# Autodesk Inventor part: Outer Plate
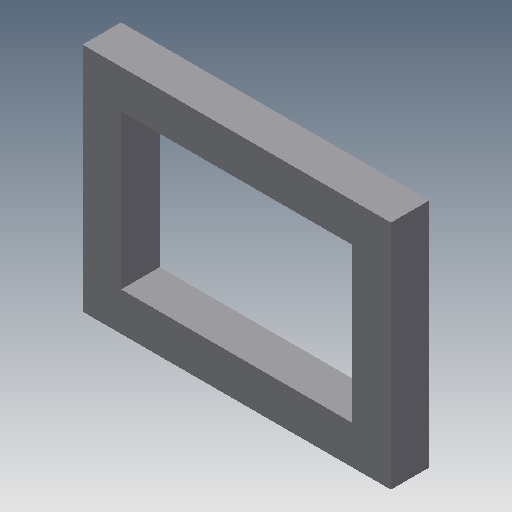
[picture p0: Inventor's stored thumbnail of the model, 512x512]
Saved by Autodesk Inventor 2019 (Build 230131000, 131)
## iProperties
Created: 2010-04
Part Number: Outer Plate
Document SubType Name: Modeling
Designer: CADSoft
Density: 1 g/cm^3
Material: Generic
Appearance: Default
Author: CADSoft
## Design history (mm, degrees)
sketch "Sketch1"
  geometry: L1 (-40, 30)-(40, 30); L2 (40, 30)-(40, -30); L3 (40, -30)-(-40, -30); L4 (-40, -30)-(-40, 30); L5 (-30, 20)-(30, 20); L6 (30, 20)-(30, -20); L7 (30, -20)-(-30, -20); L8 (-30, -20)-(-30, 20); 1 further point
  constraints: 16 end point, 4 parallel, 2 horizontal, 2 perpendicular
  dimensions: "d0" = 80 distance of L1.start L1.end; "d1" = 60 distance of L5.start L5.end; "d2" = 10 distance between parallel lines of L4 L8; "d3" = 10 distance between parallel lines of L1 L5; "d4" = 40 distance of L7.end L5.start; "d5" = 60 distance of L3.end L1.start
extrude "Extrusion1" new body sketch "Sketch1" distance "d8" = 10; taper "d9" = 0 deg
body "Solid1"
